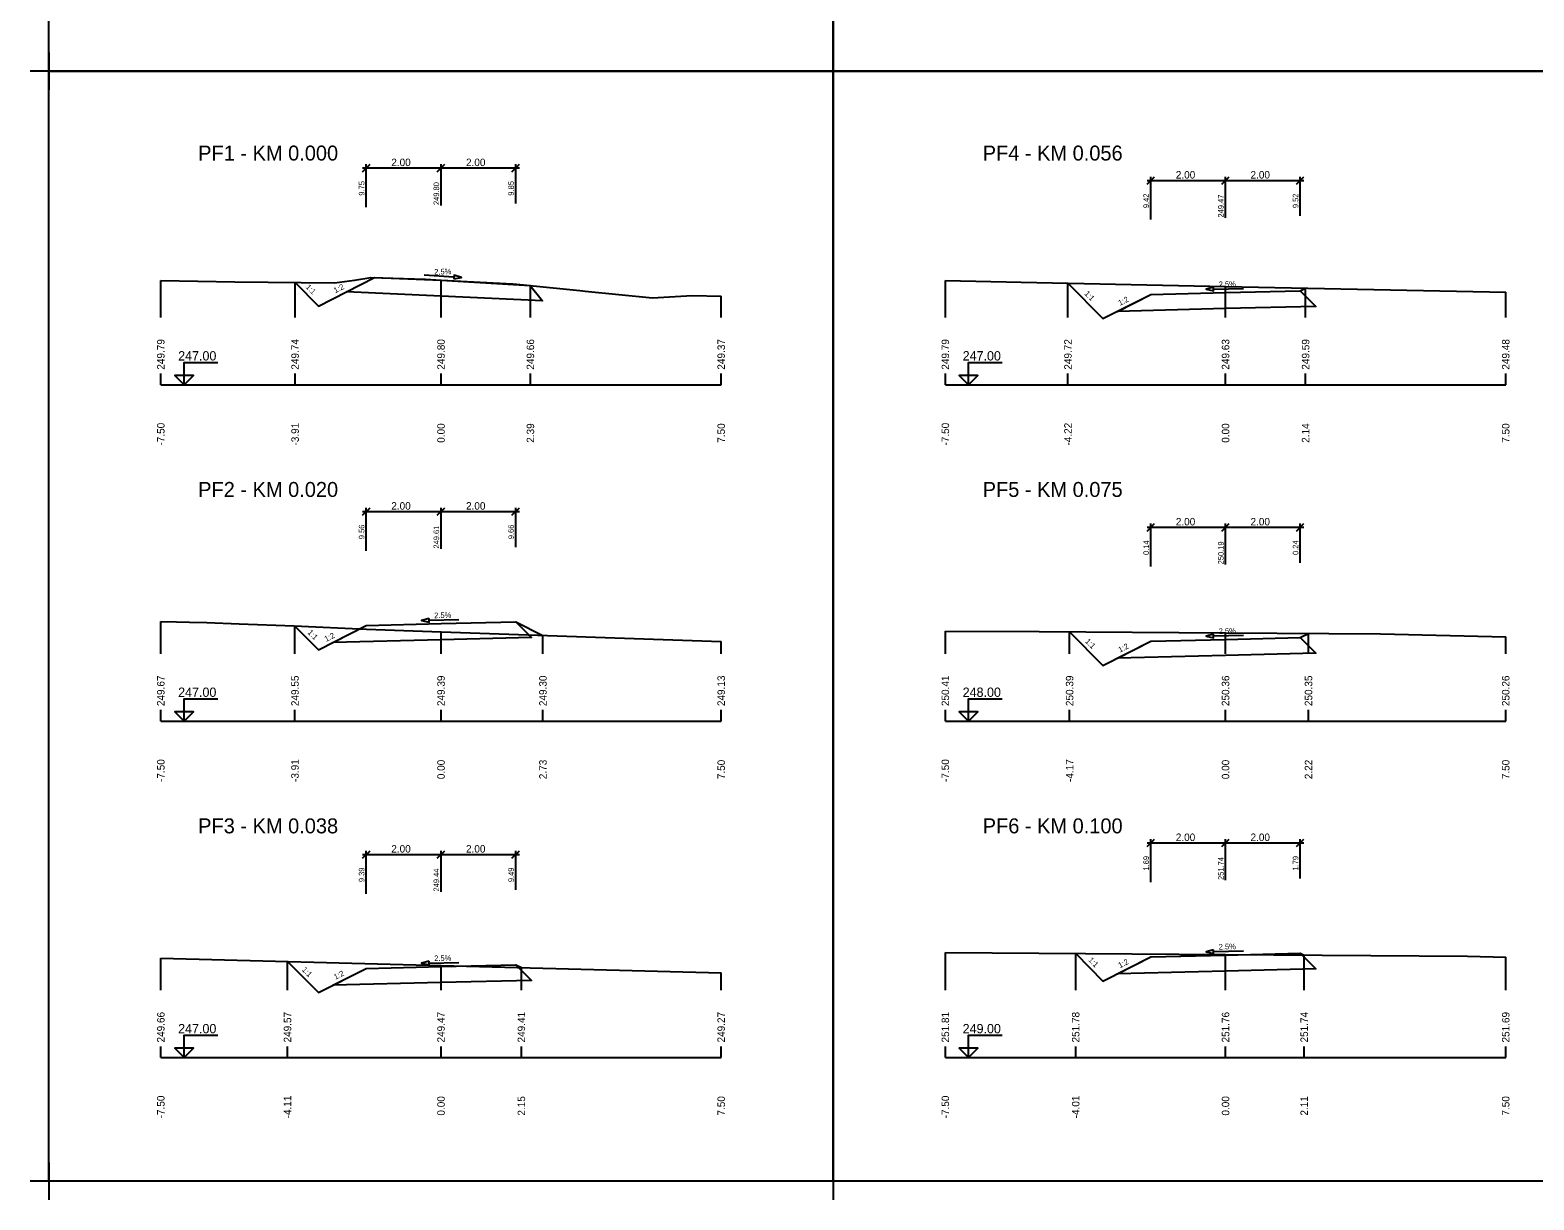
# Model space of a CAD drawing. Extents: x -1895 to 2525, y -19 to 585.
# Drawn here: x -1894.9 to -1492.4, y -19.1 to 293.9 of the extents above; entities that cross this region are included whole.
import ezdxf

# ---------------------------------------------------------------- set-up
doc = ezdxf.new("R2010")
doc.units = 0
for name, color, linetype in [('KOTA', 7, 'Continuous'), ('KOTA_DELKY', 7, 'Continuous'), ('KOTA_DELKY_CONT', 7, 'Continuous'), ('NS_TELESO_VOZOVKY', 7, 'Continuous'), ('NS_V_PF', 7, 'Continuous'), ('REZY_PF_PUVODNI', 7, 'Continuous'), ('SESTAVY_REZU_PF', 7, 'Continuous'), ('SKLON', 7, 'Continuous'), ('SVK', 7, 'Continuous')]:
    doc.layers.add(name, color=color, linetype=linetype)

msp = doc.modelspace()

# ---------------------------------------------------------------- linework, layer by layer
for p, q in [((-1889.95, 287.93), (-1889.95, 277.93)), ((-1889.95, 287.93), (-1889.95, 277.93)), ((-1889.95, 287.93), (-1889.95, 277.93)), ((-1889.95, 287.93), (-1889.95, 277.93)), ((-1679.95, 287.93), (-1679.95, 277.93)), ((-1679.95, 287.93), (-1679.95, 277.93)), ((-1679.95, 287.93), (-1679.95, 277.93)), ((-1679.95, 287.93), (-1679.95, 277.93)), ((-1884.95, 282.93), (-1894.95, 282.93)), ((-1884.95, 282.93), (-1894.95, 282.93)), ((-1884.95, 282.93), (-1894.95, 282.93)), ((-1884.95, 282.93), (-1894.95, 282.93)), ((-1674.95, 282.93), (-1684.95, 282.93)), ((-1674.95, 282.93), (-1684.95, 282.93)), ((-1674.95, 282.93), (-1684.95, 282.93)), ((-1674.95, 282.93), (-1684.95, 282.93)), ((-1889.95, -9.07), (-1889.95, -19.07)), ((-1889.95, -9.07), (-1889.95, -19.07)), ((-1679.95, -9.07), (-1679.95, -19.07)), ((-1679.95, -9.07), (-1679.95, -19.07)), ((-1884.95, -14.07), (-1894.95, -14.07)), ((-1884.95, -14.07), (-1894.95, -14.07)), ((-1674.95, -14.07), (-1684.95, -14.07)), ((-1674.95, -14.07), (-1684.95, -14.07))]:
    msp.add_line(p, q)
for points in [[(-1889.95, 579.93), (-1679.95, 579.93), (-1679.95, 282.93), (-1889.95, 282.93)], [(-1679.95, 579.93), (-1469.95, 579.93), (-1469.95, 282.93), (-1679.95, 282.93)], [(-1889.95, 282.93), (-1679.95, 282.93), (-1679.95, -14.07), (-1889.95, -14.07)], [(-1679.95, 282.93), (-1469.95, 282.93), (-1469.95, -14.07), (-1679.95, -14.07)]]:
    msp.add_lwpolyline(points, close=True)
at = {"layer": 'KOTA'}
for points in [[(-1853.73, 201.5), (-1856.23, 201.5), (-1853.73, 199), (-1853.73, 205), (-1844.73, 205)], [(-1853.73, 199), (-1851.23, 201.5), (-1853.73, 201.5)], [(-1643.73, 201.5), (-1646.23, 201.5), (-1643.73, 199), (-1643.73, 205), (-1634.73, 205)], [(-1643.73, 199), (-1641.23, 201.5), (-1643.73, 201.5)], [(-1853.73, 111.5), (-1856.23, 111.5), (-1853.73, 109), (-1853.73, 115), (-1844.73, 115)], [(-1643.73, 111.5), (-1646.23, 111.5), (-1643.73, 109), (-1643.73, 115), (-1634.73, 115)], [(-1853.73, 109), (-1851.23, 111.5), (-1853.73, 111.5)], [(-1643.73, 109), (-1641.23, 111.5), (-1643.73, 111.5)], [(-1853.73, 21.5), (-1856.23, 21.5), (-1853.73, 19), (-1853.73, 25), (-1844.73, 25)], [(-1643.73, 21.5), (-1646.23, 21.5), (-1643.73, 19), (-1643.73, 25), (-1634.73, 25)], [(-1853.73, 19), (-1851.23, 21.5), (-1853.73, 21.5)], [(-1643.73, 19), (-1641.23, 21.5), (-1643.73, 21.5)]]:
    msp.add_lwpolyline(points, dxfattribs=at)
at = {"layer": 'KOTA_DELKY'}
for points in [[(-1805.95, 256.01), (-1803.95, 258.01)], [(-1804.95, 246.51), (-1804.95, 258.01)], [(-1785.95, 256.01), (-1783.95, 258.01)], [(-1785.95, 256.01), (-1783.95, 258.01)], [(-1784.95, 247.01), (-1784.95, 258.01)], [(-1784.95, 247.01), (-1784.95, 258.01)], [(-1765.95, 256.01), (-1763.95, 258.01)], [(-1764.95, 247.51), (-1764.95, 258.01)], [(-1805.95, 257.01), (-1783.95, 257.01)], [(-1785.95, 257.01), (-1763.95, 257.01)], [(-1595.95, 252.68), (-1593.95, 254.68)], [(-1595.95, 253.68), (-1573.95, 253.68)], [(-1594.95, 243.18), (-1594.95, 254.68)], [(-1575.95, 252.68), (-1573.95, 254.68)], [(-1575.95, 252.68), (-1573.95, 254.68)], [(-1575.95, 253.68), (-1553.95, 253.68)], [(-1574.95, 243.68), (-1574.95, 254.68)], [(-1574.95, 243.68), (-1574.95, 254.68)], [(-1555.95, 252.68), (-1553.95, 254.68)], [(-1554.95, 244.18), (-1554.95, 254.68)], [(-1805.95, 164.1), (-1803.95, 166.1)], [(-1805.95, 165.1), (-1783.95, 165.1)], [(-1804.95, 154.6), (-1804.95, 166.1)], [(-1785.95, 164.1), (-1783.95, 166.1)], [(-1785.95, 164.1), (-1783.95, 166.1)], [(-1785.95, 165.1), (-1763.95, 165.1)], [(-1784.95, 155.1), (-1784.95, 166.1)], [(-1784.95, 155.1), (-1784.95, 166.1)], [(-1765.95, 164.1), (-1763.95, 166.1)], [(-1764.95, 155.6), (-1764.95, 166.1)], [(-1595.95, 159.88), (-1593.95, 161.88)], [(-1594.95, 150.38), (-1594.95, 161.88)], [(-1575.95, 159.88), (-1573.95, 161.88)], [(-1575.95, 159.88), (-1573.95, 161.88)], [(-1574.95, 150.88), (-1574.95, 161.88)], [(-1574.95, 150.88), (-1574.95, 161.88)], [(-1555.95, 159.88), (-1553.95, 161.88)], [(-1554.95, 151.38), (-1554.95, 161.88)], [(-1595.95, 160.88), (-1573.95, 160.88)], [(-1575.95, 160.88), (-1553.95, 160.88)], [(-1595.95, 75.45), (-1593.95, 77.45)], [(-1594.95, 65.95), (-1594.95, 77.45)], [(-1575.95, 75.45), (-1573.95, 77.45)], [(-1575.95, 75.45), (-1573.95, 77.45)], [(-1574.95, 66.45), (-1574.95, 77.45)], [(-1574.95, 66.45), (-1574.95, 77.45)], [(-1555.95, 75.45), (-1553.95, 77.45)], [(-1554.95, 66.95), (-1554.95, 77.45)], [(-1805.95, 72.36), (-1803.95, 74.36)], [(-1805.95, 73.36), (-1783.95, 73.36)], [(-1804.95, 62.86), (-1804.95, 74.36)], [(-1785.95, 72.36), (-1783.95, 74.36)], [(-1785.95, 72.36), (-1783.95, 74.36)], [(-1785.95, 73.36), (-1763.95, 73.36)], [(-1784.95, 63.36), (-1784.95, 74.36)], [(-1784.95, 63.36), (-1784.95, 74.36)], [(-1765.95, 72.36), (-1763.95, 74.36)], [(-1764.95, 63.86), (-1764.95, 74.36)], [(-1595.95, 76.45), (-1573.95, 76.45)], [(-1575.95, 76.45), (-1553.95, 76.45)]]:
    msp.add_lwpolyline(points, dxfattribs=at)
at = {"layer": 'NS_TELESO_VOZOVKY'}
for points in [[(-1784.95, 227.01), (-1761.06, 225.58), (-1761.06, 225.58), (-1757.74, 221.46), (-1784.95, 222.71), (-1810.25, 223.86), (-1802.75, 227.69), (-1802.75, 227.69), (-1784.95, 227.01)], [(-1574.95, 223.68), (-1554.95, 224.18), (-1554.95, 224.18), (-1550.75, 219.98), (-1574.95, 219.38), (-1603.89, 218.65), (-1594.95, 223.18), (-1594.95, 223.18), (-1574.95, 223.68)], [(-1784.95, 135.1), (-1764.95, 135.6), (-1764.95, 135.6), (-1760.75, 131.4), (-1784.95, 130.8), (-1813.89, 130.08), (-1804.95, 134.6), (-1804.95, 134.6), (-1784.95, 135.1)], [(-1574.95, 130.88), (-1554.95, 131.38), (-1554.95, 131.38), (-1550.75, 127.19), (-1574.95, 126.58), (-1603.89, 125.86), (-1594.95, 130.38), (-1594.95, 130.38), (-1574.95, 130.88)], [(-1574.95, 46.45), (-1554.95, 46.95), (-1554.95, 46.95), (-1550.75, 42.75), (-1574.95, 42.15), (-1603.89, 41.43), (-1594.95, 45.95), (-1594.95, 45.95), (-1574.95, 46.45)], [(-1784.95, 43.36), (-1764.95, 43.86), (-1764.95, 43.86), (-1760.75, 39.66), (-1784.95, 39.06), (-1813.89, 38.34), (-1804.95, 42.86), (-1804.95, 42.86), (-1784.95, 43.36)]]:
    msp.add_lwpolyline(points, dxfattribs=at)
at = {"layer": 'NS_V_PF'}
for points in [[(-1824.01, 226.35), (-1817.76, 220.04), (-1802.75, 227.69), (-1802.75, 227.69), (-1784.95, 227.01), (-1765.74, 225.97), (-1765.74, 225.97), (-1761.02, 225.55)], [(-1617.13, 226.17), (-1607.76, 216.7), (-1594.95, 223.18), (-1594.95, 223.18), (-1574.95, 223.68), (-1554.95, 224.18), (-1554.95, 224.18), (-1553.52, 224.89)], [(-1824.04, 134.46), (-1817.76, 128.12), (-1804.95, 134.6), (-1804.95, 134.6), (-1784.95, 135.1), (-1764.95, 135.6), (-1764.95, 135.6), (-1757.67, 131.96)], [(-1616.69, 132.93), (-1607.76, 123.9), (-1594.95, 130.38), (-1594.95, 130.38), (-1574.95, 130.88), (-1554.95, 131.38), (-1554.95, 131.38), (-1552.74, 132.49)], [(-1826.04, 44.75), (-1817.76, 36.38), (-1804.95, 42.86), (-1804.95, 42.86), (-1784.95, 43.36), (-1764.95, 43.86), (-1764.95, 43.86), (-1763.44, 43.11)], [(-1615.06, 46.84), (-1607.76, 39.47), (-1594.95, 45.95), (-1594.95, 45.95), (-1574.95, 46.45), (-1554.95, 46.95), (-1554.95, 46.95), (-1553.89, 46.42)]]:
    msp.add_lwpolyline(points, dxfattribs=at)
at = {"layer": 'REZY_PF_PUVODNI'}
for points in [[(-1859.95, 226.88), (-1840.11, 226.52), (-1813.43, 226.24), (-1808.08, 226.99), (-1803.74, 227.74), (-1789.08, 227.24), (-1784.95, 227.01), (-1765.74, 225.97), (-1759.43, 225.41), (-1747.75, 224.26), (-1746.32, 224.01), (-1728.38, 222.24), (-1717.72, 222.9), (-1709.95, 222.67)], [(-1649.95, 226.92), (-1629.68, 226.42), (-1574.95, 225.32), (-1499.95, 223.82)], [(-1859.95, 135.68), (-1855.79, 135.61), (-1852.29, 135.53), (-1847.59, 135.45), (-1838.96, 135.04), (-1824.3, 134.48), (-1804.93, 133.62), (-1784.95, 132.92), (-1709.95, 130.28)], [(-1649.95, 133.07), (-1624.86, 132.99), (-1574.95, 132.64), (-1533.46, 132.35), (-1499.95, 131.59)], [(-1859.95, 45.64), (-1784.95, 43.67), (-1709.95, 41.7)], [(-1649.95, 47.09), (-1574.95, 46.57), (-1510.19, 46.12), (-1499.95, 45.89)]]:
    msp.add_lwpolyline(points, dxfattribs=at)
at = {"layer": 'SESTAVY_REZU_PF'}
for points in [[(-1859.95, 199), (-1709.95, 199)], [(-1649.95, 199), (-1499.95, 199)], [(-1859.95, 109), (-1709.95, 109)], [(-1649.95, 109), (-1499.95, 109)], [(-1859.95, 19), (-1709.95, 19)], [(-1649.95, 19), (-1499.95, 19)]]:
    msp.add_lwpolyline(points, dxfattribs=at)
at = {"layer": 'SKLON'}
for points in [[(-1781.48, 227.84), (-1789.47, 228.33)], [(-1781.51, 227.34), (-1779.49, 227.72), (-1781.45, 228.34), (-1781.51, 227.34)], [(-1578.16, 225.1), (-1580.15, 224.55), (-1578.14, 224.1), (-1578.16, 225.1)], [(-1578.15, 224.6), (-1570.15, 224.8)], [(-1788.16, 136.52), (-1790.15, 135.97), (-1788.14, 135.52), (-1788.16, 136.52)], [(-1788.15, 136.02), (-1780.15, 136.22)], [(-1578.16, 132.3), (-1580.15, 131.75), (-1578.14, 131.3), (-1578.16, 132.3)], [(-1578.15, 131.8), (-1570.15, 132)], [(-1788.16, 44.78), (-1790.15, 44.23), (-1788.14, 43.78), (-1788.16, 44.78)], [(-1788.15, 44.28), (-1780.15, 44.48)], [(-1578.16, 47.87), (-1580.15, 47.32), (-1578.14, 46.87), (-1578.16, 47.87)], [(-1578.15, 47.37), (-1570.15, 47.57)]]:
    msp.add_lwpolyline(points, dxfattribs=at)
at = {"layer": 'SVK'}
for points in [[(-1859.95, 217), (-1859.95, 226.88)], [(-1824.01, 217), (-1824.01, 226.35)], [(-1784.95, 217), (-1784.95, 227.01)], [(-1761.02, 217), (-1761.02, 225.55)], [(-1649.95, 217), (-1649.95, 226.92)], [(-1617.13, 217), (-1617.13, 226.17)], [(-1709.95, 217), (-1709.95, 222.67)], [(-1574.95, 217), (-1574.95, 225.32)], [(-1553.52, 217), (-1553.52, 224.89)], [(-1499.95, 217), (-1499.95, 223.82)], [(-1859.95, 199), (-1859.95, 202)], [(-1824.01, 199), (-1824.01, 202)], [(-1784.95, 199), (-1784.95, 202)], [(-1761.02, 199), (-1761.02, 202)], [(-1709.95, 199), (-1709.95, 202)], [(-1649.95, 199), (-1649.95, 202)], [(-1617.13, 199), (-1617.13, 202)], [(-1574.95, 199), (-1574.95, 202)], [(-1553.52, 199), (-1553.52, 202)], [(-1499.95, 199), (-1499.95, 202)], [(-1859.95, 127), (-1859.95, 135.68)], [(-1824.04, 127), (-1824.04, 134.46)], [(-1784.95, 127), (-1784.95, 132.92)], [(-1649.95, 127), (-1649.95, 133.07)], [(-1616.69, 127), (-1616.69, 132.93)], [(-1757.67, 127), (-1757.67, 131.96)], [(-1709.95, 127), (-1709.95, 130.28)], [(-1574.95, 127), (-1574.95, 132.64)], [(-1552.74, 127), (-1552.74, 132.49)], [(-1499.95, 127), (-1499.95, 131.59)], [(-1859.95, 109), (-1859.95, 112)], [(-1824.04, 109), (-1824.04, 112)], [(-1784.95, 109), (-1784.95, 112)], [(-1757.67, 109), (-1757.67, 112)], [(-1709.95, 109), (-1709.95, 112)], [(-1649.95, 109), (-1649.95, 112)], [(-1616.69, 109), (-1616.69, 112)], [(-1574.95, 109), (-1574.95, 112)], [(-1552.74, 109), (-1552.74, 112)], [(-1499.95, 109), (-1499.95, 112)], [(-1859.95, 37), (-1859.95, 45.64)], [(-1826.04, 37), (-1826.04, 44.75)], [(-1649.95, 37), (-1649.95, 47.09)], [(-1615.06, 37), (-1615.06, 46.84)], [(-1574.95, 37), (-1574.95, 46.57)], [(-1553.89, 37), (-1553.89, 46.42)], [(-1499.95, 37), (-1499.95, 45.89)], [(-1784.95, 37), (-1784.95, 43.67)], [(-1763.44, 37), (-1763.44, 43.11)], [(-1709.95, 37), (-1709.95, 41.7)], [(-1859.95, 19), (-1859.95, 22)], [(-1826.04, 19), (-1826.04, 22)], [(-1784.95, 19), (-1784.95, 22)], [(-1763.44, 19), (-1763.44, 22)], [(-1709.95, 19), (-1709.95, 22)], [(-1649.95, 19), (-1649.95, 22)], [(-1615.06, 19), (-1615.06, 22)], [(-1574.95, 19), (-1574.95, 22)], [(-1553.89, 19), (-1553.89, 22)], [(-1499.95, 19), (-1499.95, 22)]]:
    msp.add_lwpolyline(points, dxfattribs=at)

# ---------------------------------------------------------------- texts
at = {"layer": 'KOTA'}
for s, p in [('247.00', (-1855.31, 205.5)), ('247.00', (-1645.31, 205.5)), ('247.00', (-1855.31, 115.5)), ('248.00', (-1645.31, 115.5)), ('247.00', (-1855.31, 25.5)), ('249.00', (-1645.31, 25.5))]:
    msp.add_text(s, height=2.5, dxfattribs=at).set_placement(p)
at = {"layer": 'KOTA_DELKY'}
for p in [(-1798.26, 257.51), (-1778.26, 257.51), (-1588.26, 254.18), (-1568.26, 254.18), (-1798.26, 165.6), (-1778.26, 165.6), (-1588.26, 161.38), (-1568.26, 161.38), (-1588.26, 76.95), (-1568.26, 76.95), (-1798.26, 73.86), (-1778.26, 73.86)]:
    msp.add_text('2.00', height=2, dxfattribs=at).set_placement(p)
at = {"layer": 'KOTA_DELKY_CONT'}
for s, p in [('9.75', (-1805.45, 249.6)), ('249.80', (-1785.45, 247.09)), ('9.85', (-1765.45, 249.6)), ('9.42', (-1595.45, 246.26)), ('249.47', (-1575.45, 243.75)), ('9.52', (-1555.45, 246.26)), ('9.56', (-1805.45, 157.69)), ('249.61', (-1785.45, 155.18)), ('9.66', (-1765.45, 157.69)), ('0.14', (-1595.45, 153.47)), ('250.19', (-1575.45, 150.96)), ('0.24', (-1555.45, 153.47)), ('1.69', (-1595.45, 69.04)), ('251.74', (-1575.45, 66.53)), ('1.79', (-1555.45, 69.04)), ('9.39', (-1805.45, 65.95)), ('249.44', (-1785.45, 63.44)), ('9.49', (-1765.45, 65.95))]:
    msp.add_text(s, height=1.5, rotation=90, dxfattribs=at).set_placement(p)
at = {"layer": 'SESTAVY_REZU_PF'}
for s, p in [('PF1 - KM 0.000', (-1849.95, 259)), ('PF4 - KM 0.056', (-1639.95, 259)), ('PF2 - KM 0.020', (-1849.95, 169)), ('PF5 - KM 0.075', (-1639.95, 169)), ('PF3 - KM 0.038', (-1849.95, 79)), ('PF6 - KM 0.100', (-1639.95, 79))]:
    msp.add_text(s, height=4, dxfattribs=at).set_placement(p)
at = {"layer": 'SKLON'}
for s, rotation, p in [('2.5%', 1.4321, (-1786.75, 228.47)), ('1:1', 314.7121, (-1821.28, 225.02)), ('1:2', 26.8233, (-1813.21, 223.46)), ('2.5%', 1.4321, (-1576.75, 225.13)), ('1:1', 314.7121, (-1612.84, 223.26)), ('1:2', 26.8233, (-1603.21, 220.12)), ('2.5%', 1.4321, (-1786.75, 136.55)), ('1:1', 314.7121, (-1820.77, 132.59)), ('2.5%', 1.4321, (-1576.75, 132.34)), ('1:2', 26.8233, (-1815.7, 130.21)), ('1:1', 314.7121, (-1612.62, 130.24)), ('1:2', 26.8233, (-1603.21, 127.32)), ('2.5%', 1.4321, (-1576.75, 47.9)), ('2.5%', 1.4321, (-1786.75, 44.81)), ('1:1', 314.7121, (-1611.8, 44.98)), ('1:2', 26.8233, (-1603.21, 42.89)), ('1:1', 314.7121, (-1822.3, 42.39)), ('1:2', 26.8233, (-1813.21, 39.8))]:
    msp.add_text(s, height=1.5, rotation=rotation, dxfattribs=at).set_placement(p)
at = {"layer": 'SVK'}
for s, p in [(' 249.79', (-1858.95, 202.3)), (' 249.74', (-1823.01, 202.3)), (' 249.80', (-1783.95, 202.3)), (' 249.66', (-1760.02, 202.3)), (' 249.37', (-1708.95, 202.3)), (' 249.79', (-1648.95, 202.3)), (' 249.72', (-1616.13, 202.3)), (' 249.63', (-1573.95, 202.3)), (' 249.59', (-1552.52, 202.3)), (' 249.48', (-1498.95, 202.3)), (' -7.50', (-1858.95, 182)), (' -3.91', (-1823.01, 182)), ('  0.00', (-1783.95, 182)), ('  2.39', (-1760.02, 182)), ('  7.50', (-1708.95, 182)), (' -7.50', (-1648.95, 182)), (' -4.22', (-1616.13, 182)), ('  0.00', (-1573.95, 182)), ('  2.14', (-1552.52, 182)), ('  7.50', (-1498.95, 182)), (' 249.67', (-1858.95, 112.3)), (' 249.55', (-1823.04, 112.3)), (' 249.39', (-1783.95, 112.3)), (' 249.30', (-1756.67, 112.3)), (' 249.13', (-1708.95, 112.3)), (' 250.41', (-1648.95, 112.3)), (' 250.39', (-1615.69, 112.3)), (' 250.36', (-1573.95, 112.3)), (' 250.35', (-1551.74, 112.3)), (' 250.26', (-1498.95, 112.3)), (' -7.50', (-1858.95, 92)), (' -3.91', (-1823.04, 92)), ('  0.00', (-1783.95, 92)), ('  2.73', (-1756.67, 92)), ('  7.50', (-1708.95, 92)), (' -7.50', (-1648.95, 92)), (' -4.17', (-1615.69, 92)), ('  0.00', (-1573.95, 92)), ('  2.22', (-1551.74, 92)), ('  7.50', (-1498.95, 92)), (' 249.66', (-1858.95, 22.3)), (' 249.57', (-1825.04, 22.3)), (' 249.47', (-1783.95, 22.3)), (' 249.41', (-1762.44, 22.3)), (' 249.27', (-1708.95, 22.3)), (' 251.81', (-1648.95, 22.3)), (' 251.78', (-1614.06, 22.3)), (' 251.76', (-1573.95, 22.3)), (' 251.74', (-1552.89, 22.3)), (' 251.69', (-1498.95, 22.3)), (' -7.50', (-1858.95, 2)), (' -4.11', (-1825.04, 2)), ('  0.00', (-1783.95, 2)), ('  2.15', (-1762.44, 2)), ('  7.50', (-1708.95, 2)), (' -7.50', (-1648.95, 2)), (' -4.01', (-1614.06, 2)), ('  0.00', (-1573.95, 2)), ('  2.11', (-1552.89, 2)), ('  7.50', (-1498.95, 2))]:
    msp.add_text(s, height=2, rotation=90, dxfattribs=at).set_placement(p)

doc.saveas('drawing.dxf')
